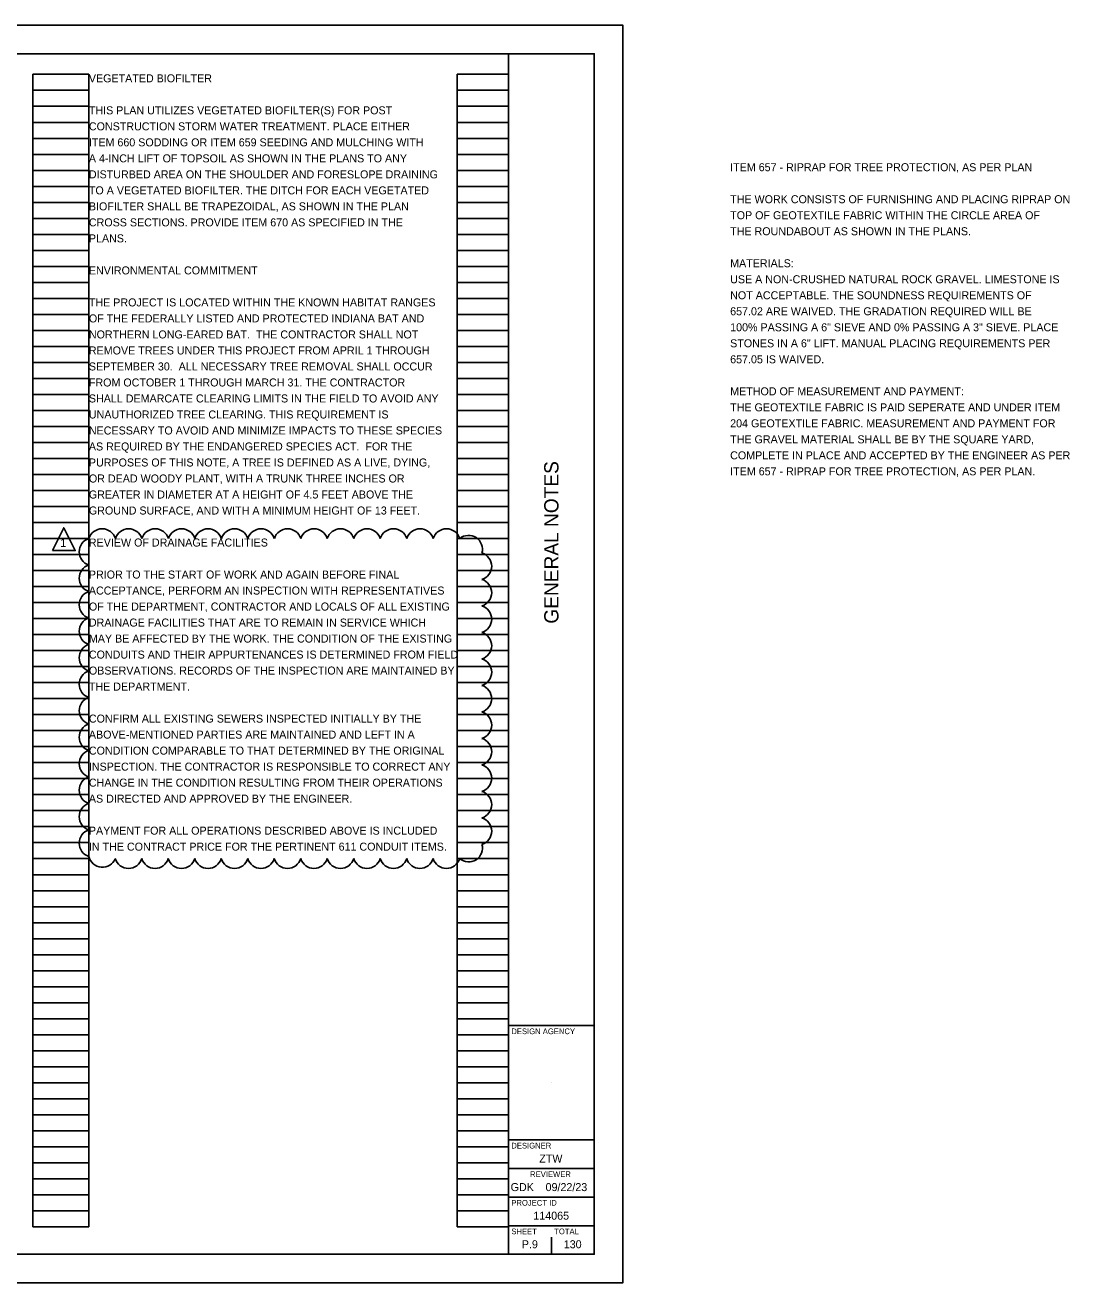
# Model space of a CAD drawing. Extents: x -20.9 to 41.8, y -2.3 to 41.6.
# Drawn here: x 23.55 to 41.82, y 0 to 22 of the extents above; entities that cross this region are included whole.
import ezdxf

# ---------------------------------------------------------------- set-up
doc = ezdxf.new("R2010")
doc.units = 0
for name, color, linetype in [('BR_P_Gen_Text', 7, 'Continuous'), ('SH_Border', 7, 'Continuous'), ('SH_Cut_Line', 7, 'Continuous'), ('SH_Data', 7, 'Continuous'), ('SH_Text', 7, 'Continuous')]:
    doc.layers.add(name, color=color, linetype=linetype)

msp = doc.modelspace()

# ---------------------------------------------------------------- linework, layer by layer
at = {"layer": 'BR_P_Gen_Text'}
msp.add_lwpolyline([(24.021, 12.808), (24.221, 13.208), (24.421, 12.808)], close=True, dxfattribs=at)
for centre, start, end in [((24.733, 12.788), 107.5, 252.5), ((24.892, 12.947), 17.5, 162.5), ((25.355, 12.947), 17.5, 162.5), ((25.819, 12.947), 17.5, 162.5), ((26.282, 12.947), 17.5, 162.5), ((26.745, 12.947), 17.5, 162.5), ((27.209, 12.947), 17.5, 162.5), ((27.672, 12.947), 17.5, 162.5), ((28.136, 12.947), 17.5, 162.5), ((28.599, 12.947), 17.5, 162.5), ((29.062, 12.947), 17.5, 162.5), ((29.526, 12.947), 17.5, 162.5), ((29.989, 12.947), 17.5, 162.5), ((30.453, 12.947), 17.5, 162.5), ((30.916, 12.947), 17.5, 162.5), ((31.302, 12.832), 344.4353, 129.4353), ((31.463, 12.535), 287.5, 72.5), ((24.733, 12.325), 107.5, 252.5), ((31.463, 12.072), 287.5, 72.5), ((24.733, 11.861), 107.5, 252.5), ((31.463, 11.609), 287.5, 72.5), ((24.733, 11.398), 107.5, 252.5), ((31.463, 11.145), 287.5, 72.5), ((24.733, 10.935), 107.5, 252.5), ((31.463, 10.682), 287.5, 72.5), ((24.733, 10.471), 107.5, 252.5), ((31.463, 10.218), 287.5, 72.5), ((24.733, 10.008), 107.5, 252.5), ((31.463, 9.755), 287.5, 72.5), ((24.733, 9.544), 107.5, 252.5), ((31.463, 9.291), 287.5, 72.5), ((24.733, 9.081), 107.5, 252.5), ((31.463, 8.828), 287.5, 72.5), ((24.733, 8.618), 107.5, 252.5), ((31.463, 8.365), 287.5, 72.5), ((24.733, 8.154), 107.5, 252.5), ((24.733, 7.691), 107.5, 252.5), ((31.463, 7.901), 287.5, 72.5), ((31.302, 7.606), 230.0934, 15.0934), ((24.897, 7.512), 192.6693, 337.6693), ((25.353, 7.493), 197.5, 342.5), ((25.817, 7.493), 197.5, 342.5), ((26.28, 7.493), 197.5, 342.5), ((26.744, 7.493), 197.5, 342.5), ((27.207, 7.493), 197.5, 342.5), ((27.67, 7.493), 197.5, 342.5), ((28.134, 7.493), 197.5, 342.5), ((28.597, 7.493), 197.5, 342.5), ((29.061, 7.493), 197.5, 342.5), ((29.524, 7.493), 197.5, 342.5), ((29.988, 7.493), 197.5, 342.5), ((30.451, 7.493), 197.5, 342.5), ((30.914, 7.493), 197.5, 342.5)]:
    msp.add_arc(centre, 0.243, start, end, dxfattribs=at)
at = {"layer": 'SH_Cut_Line'}
for p, q in [((32, 0.5), (32, 21.5)), ((32, 4.5), (33.5, 4.5)), ((32, 2.5), (33.5, 2.5)), ((32, 2), (33.5, 2)), ((32, 1.5), (33.5, 1.5)), ((32, 1), (33.5, 1))]:
    msp.add_line(p, q, dxfattribs=at)
msp.add_lwpolyline([(1.5, 21.5), (33.5, 21.5), (33.5, 0.5), (1.5, 0.5)], close=True, dxfattribs=at)
at = {"layer": 'SH_Data'}
for p, q in [((23.68, 0.98), (23.68, 21.14)), ((23.68, 21.14), (24.66, 21.14)), ((24.66, 0.98), (24.66, 21.14)), ((31.1, 0.98), (31.1, 21.14)), ((31.1, 21.14), (32, 21.14)), ((32, 0.98), (32, 21.14)), ((23.68, 20.86), (24.66, 20.86)), ((31.1, 20.86), (32, 20.86)), ((23.68, 20.58), (24.66, 20.58)), ((31.1, 20.58), (32, 20.58)), ((23.68, 20.3), (24.66, 20.3)), ((31.1, 20.3), (32, 20.3)), ((23.68, 20.02), (24.66, 20.02)), ((31.1, 20.02), (32, 20.02)), ((23.68, 19.74), (24.66, 19.74)), ((31.1, 19.74), (32, 19.74)), ((23.68, 19.46), (24.66, 19.46)), ((31.1, 19.46), (32, 19.46)), ((23.68, 19.18), (24.66, 19.18)), ((31.1, 19.18), (32, 19.18)), ((23.68, 18.9), (24.66, 18.9)), ((31.1, 18.9), (32, 18.9)), ((23.68, 18.62), (24.66, 18.62)), ((31.1, 18.62), (32, 18.62)), ((23.68, 18.34), (24.66, 18.34)), ((31.1, 18.34), (32, 18.34)), ((23.68, 18.06), (24.66, 18.06)), ((31.1, 18.06), (32, 18.06)), ((23.68, 17.78), (24.66, 17.78)), ((31.1, 17.78), (32, 17.78)), ((23.68, 17.5), (24.66, 17.5)), ((31.1, 17.5), (32, 17.5)), ((23.68, 17.22), (24.66, 17.22)), ((31.1, 17.22), (32, 17.22)), ((23.68, 16.94), (24.66, 16.94)), ((31.1, 16.94), (32, 16.94)), ((23.68, 16.66), (24.66, 16.66)), ((31.1, 16.66), (32, 16.66)), ((23.68, 16.38), (24.66, 16.38)), ((31.1, 16.38), (32, 16.38)), ((23.68, 16.1), (24.66, 16.1)), ((31.1, 16.1), (32, 16.1)), ((23.68, 15.82), (24.66, 15.82)), ((31.1, 15.82), (32, 15.82)), ((23.68, 15.54), (24.66, 15.54)), ((31.1, 15.54), (32, 15.54)), ((23.68, 15.26), (24.66, 15.26)), ((31.1, 15.26), (32, 15.26)), ((23.68, 14.98), (24.66, 14.98)), ((31.1, 14.98), (32, 14.98)), ((23.68, 14.7), (24.66, 14.7)), ((31.1, 14.7), (32, 14.7)), ((23.68, 14.42), (24.66, 14.42)), ((31.1, 14.42), (32, 14.42)), ((23.68, 14.14), (24.66, 14.14)), ((31.1, 14.14), (32, 14.14)), ((23.68, 13.86), (24.66, 13.86)), ((31.1, 13.86), (32, 13.86)), ((23.68, 13.58), (24.66, 13.58)), ((31.1, 13.58), (32, 13.58)), ((23.68, 13.3), (24.66, 13.3)), ((31.1, 13.3), (32, 13.3)), ((23.68, 13.02), (24.66, 13.02)), ((31.1, 13.02), (32, 13.02)), ((23.68, 12.74), (24.66, 12.74)), ((31.1, 12.74), (32, 12.74)), ((23.68, 12.46), (24.66, 12.46)), ((31.1, 12.46), (32, 12.46)), ((23.68, 12.18), (24.66, 12.18)), ((31.1, 12.18), (32, 12.18)), ((23.68, 11.9), (24.66, 11.9)), ((31.1, 11.9), (32, 11.9)), ((23.68, 11.62), (24.66, 11.62)), ((31.1, 11.62), (32, 11.62)), ((23.68, 11.34), (24.66, 11.34)), ((31.1, 11.34), (32, 11.34)), ((23.68, 11.06), (24.66, 11.06)), ((31.1, 11.06), (32, 11.06)), ((23.68, 10.78), (24.66, 10.78)), ((31.1, 10.78), (32, 10.78)), ((23.68, 10.5), (24.66, 10.5)), ((31.1, 10.5), (32, 10.5)), ((23.68, 10.22), (24.66, 10.22)), ((31.1, 10.22), (32, 10.22)), ((23.68, 9.94), (24.66, 9.94)), ((31.1, 9.94), (32, 9.94)), ((23.68, 9.66), (24.66, 9.66)), ((31.1, 9.66), (32, 9.66)), ((23.68, 9.38), (24.66, 9.38)), ((31.1, 9.38), (32, 9.38)), ((23.68, 9.1), (24.66, 9.1)), ((31.1, 9.1), (32, 9.1)), ((23.68, 8.82), (24.66, 8.82)), ((31.1, 8.82), (32, 8.82)), ((23.68, 8.54), (24.66, 8.54)), ((31.1, 8.54), (32, 8.54)), ((23.68, 8.26), (24.66, 8.26)), ((31.1, 8.26), (32, 8.26)), ((23.68, 7.98), (24.66, 7.98)), ((31.1, 7.98), (32, 7.98)), ((23.68, 7.7), (24.66, 7.7)), ((31.1, 7.7), (32, 7.7)), ((23.68, 7.42), (24.66, 7.42)), ((31.1, 7.42), (32, 7.42)), ((23.68, 7.14), (24.66, 7.14)), ((31.1, 7.14), (32, 7.14)), ((23.68, 6.86), (24.66, 6.86)), ((31.1, 6.86), (32, 6.86)), ((23.68, 6.58), (24.66, 6.58)), ((31.1, 6.58), (32, 6.58)), ((23.68, 6.3), (24.66, 6.3)), ((31.1, 6.3), (32, 6.3)), ((23.68, 6.02), (24.66, 6.02)), ((31.1, 6.02), (32, 6.02)), ((23.68, 5.74), (24.66, 5.74)), ((31.1, 5.74), (32, 5.74)), ((23.68, 5.46), (24.66, 5.46)), ((31.1, 5.46), (32, 5.46)), ((23.68, 5.18), (24.66, 5.18)), ((31.1, 5.18), (32, 5.18)), ((23.68, 4.9), (24.66, 4.9)), ((31.1, 4.9), (32, 4.9)), ((23.68, 4.62), (24.66, 4.62)), ((31.1, 4.62), (32, 4.62)), ((23.68, 4.34), (24.66, 4.34)), ((31.1, 4.34), (32, 4.34)), ((23.68, 4.06), (24.66, 4.06)), ((31.1, 4.06), (32, 4.06)), ((23.68, 3.78), (24.66, 3.78)), ((31.1, 3.78), (32, 3.78)), ((23.68, 3.5), (24.66, 3.5)), ((31.1, 3.5), (32, 3.5)), ((32.75, 3.5), (32.75, 3.5)), ((23.68, 3.22), (24.66, 3.22)), ((31.1, 3.22), (32, 3.22)), ((23.68, 2.94), (24.66, 2.94)), ((31.1, 2.94), (32, 2.94)), ((23.68, 2.66), (24.66, 2.66)), ((31.1, 2.66), (32, 2.66)), ((23.68, 2.38), (24.66, 2.38)), ((31.1, 2.38), (32, 2.38)), ((23.68, 2.1), (24.66, 2.1)), ((31.1, 2.1), (32, 2.1)), ((23.68, 1.82), (24.66, 1.82)), ((31.1, 1.82), (32, 1.82)), ((23.68, 1.54), (24.66, 1.54)), ((31.1, 1.54), (32, 1.54)), ((23.68, 1.26), (24.66, 1.26)), ((31.1, 1.26), (32, 1.26)), ((23.68, 0.98), (24.66, 0.98)), ((31.1, 0.98), (32, 0.98)), ((32.375, 0.675), (32.375, 0.675)), ((32.75, 0.5), (32.75, 0.8))]:
    msp.add_line(p, q, dxfattribs=at)
at = {"layer": 'SH_Text'}
msp.add_lwpolyline([(0, 0), (34, 0), (34, 22), (0, 22)], close=True, dxfattribs=at)

# ---------------------------------------------------------------- texts
at = {"layer": 'BR_P_Gen_Text'}
msp.add_text('1', height=0.14, dxfattribs=at).set_placement((24.159, 12.874))
at = {"layer": 'SH_Border'}
for s, p in [('VEGETATED BIOFILTER', (24.66, 21)), ('THIS PLAN UTILIZES VEGETATED BIOFILTER(S) FOR POST', (24.66, 20.44)), ('CONSTRUCTION STORM WATER TREATMENT. PLACE EITHER', (24.66, 20.16)), ('ITEM 660 SODDING OR ITEM 659 SEEDING AND MULCHING WITH', (24.66, 19.88)), ('A 4-INCH LIFT OF TOPSOIL AS SHOWN IN THE PLANS TO ANY', (24.66, 19.6)), ('ITEM 657 - RIPRAP FOR TREE PROTECTION, AS PER PLAN', (35.878, 19.445)), ('DISTURBED AREA ON THE SHOULDER AND FORESLOPE DRAINING', (24.66, 19.32)), ('TO A VEGETATED BIOFILTER. THE DITCH FOR EACH VEGETATED', (24.66, 19.04)), ('THE WORK CONSISTS OF FURNISHING AND PLACING RIPRAP ON ', (35.878, 18.885)), ('BIOFILTER SHALL BE TRAPEZOIDAL, AS SHOWN IN THE PLAN', (24.66, 18.76)), ('TOP OF GEOTEXTILE FABRIC WITHIN THE CIRCLE AREA OF', (35.878, 18.605)), ('CROSS SECTIONS. PROVIDE ITEM 670 AS SPECIFIED IN THE', (24.66, 18.48)), ('PLANS.', (24.66, 18.2)), ('THE ROUNDABOUT AS SHOWN IN THE PLANS.', (35.878, 18.325)), ('MATERIALS:', (35.878, 17.765)), ('ENVIRONMENTAL COMMITMENT', (24.66, 17.64)), ('USE A NON-CRUSHED NATURAL ROCK GRAVEL. LIMESTONE IS', (35.878, 17.485)), ('THE PROJECT IS LOCATED WITHIN THE KNOWN HABITAT RANGES ', (24.66, 17.08)), ('NOT ACCEPTABLE. THE SOUNDNESS REQUIREMENTS OF ', (35.878, 17.205)), ('OF THE FEDERALLY LISTED AND PROTECTED INDIANA BAT AND ', (24.66, 16.8)), ('657.02 ARE WAIVED. THE GRADATION REQUIRED WILL BE ', (35.878, 16.925)), ('100% PASSING A 6" SIEVE AND 0% PASSING A 3" SIEVE. PLACE', (35.878, 16.645)), ('NORTHERN LONG-EARED BAT.  THE CONTRACTOR SHALL NOT ', (24.66, 16.52)), ('STONES IN A 6" LIFT. MANUAL PLACING REQUIREMENTS PER', (35.878, 16.365)), ('REMOVE TREES UNDER THIS PROJECT FROM APRIL 1 THROUGH ', (24.66, 16.24)), ('SEPTEMBER 30.  ALL NECESSARY TREE REMOVAL SHALL OCCUR ', (24.66, 15.96)), ('657.05 IS WAIVED.', (35.878, 16.085)), ('FROM OCTOBER 1 THROUGH MARCH 31. THE CONTRACTOR ', (24.66, 15.68)), ('METHOD OF MEASUREMENT AND PAYMENT:', (35.878, 15.525)), ('SHALL DEMARCATE CLEARING LIMITS IN THE FIELD TO AVOID ANY ', (24.66, 15.4)), ('UNAUTHORIZED TREE CLEARING. THIS REQUIREMENT IS ', (24.66, 15.12)), ('THE GEOTEXTILE FABRIC IS PAID SEPERATE AND UNDER ITEM', (35.878, 15.245)), ('NECESSARY TO AVOID AND MINIMIZE IMPACTS TO THESE SPECIES ', (24.66, 14.84)), ('204 GEOTEXTILE FABRIC. MEASUREMENT AND PAYMENT FOR', (35.878, 14.965)), ('THE GRAVEL MATERIAL SHALL BE BY THE SQUARE YARD,', (35.878, 14.685)), ('AS REQUIRED BY THE ENDANGERED SPECIES ACT.  FOR THE ', (24.66, 14.56)), ('COMPLETE IN PLACE AND ACCEPTED BY THE ENGINEER AS PER ', (35.878, 14.405)), ('PURPOSES OF THIS NOTE, A TREE IS DEFINED AS A LIVE, DYING, ', (24.66, 14.28)), ('OR DEAD WOODY PLANT, WITH A TRUNK THREE INCHES OR ', (24.66, 14)), ('ITEM 657 - RIPRAP FOR TREE PROTECTION, AS PER PLAN.', (35.878, 14.125)), ('GREATER IN DIAMETER AT A HEIGHT OF 4.5 FEET ABOVE THE ', (24.66, 13.72)), ('GROUND SURFACE, AND WITH A MINIMUM HEIGHT OF 13 FEET. ', (24.66, 13.44)), ('REVIEW OF DRAINAGE FACILITIES', (24.66, 12.88)), ('PRIOR TO THE START OF WORK AND AGAIN BEFORE FINAL', (24.66, 12.32)), ('ACCEPTANCE, PERFORM AN INSPECTION WITH REPRESENTATIVES', (24.66, 12.04)), ('OF THE DEPARTMENT, CONTRACTOR AND LOCALS OF ALL EXISTING', (24.66, 11.76)), ('DRAINAGE FACILITIES THAT ARE TO REMAIN IN SERVICE WHICH', (24.66, 11.48)), ('MAY BE AFFECTED BY THE WORK. THE CONDITION OF THE EXISTING', (24.66, 11.2)), ('CONDUITS AND THEIR APPURTENANCES IS DETERMINED FROM FIELD', (24.66, 10.92)), ('OBSERVATIONS. RECORDS OF THE INSPECTION ARE MAINTAINED BY', (24.66, 10.64)), ('THE DEPARTMENT.', (24.66, 10.36)), ('CONFIRM ALL EXISTING SEWERS INSPECTED INITIALLY BY THE', (24.66, 9.8)), ('ABOVE-MENTIONED PARTIES ARE MAINTAINED AND LEFT IN A', (24.66, 9.52)), ('CONDITION COMPARABLE TO THAT DETERMINED BY THE ORIGINAL', (24.66, 9.24)), ('INSPECTION. THE CONTRACTOR IS RESPONSIBLE TO CORRECT ANY', (24.66, 8.96)), ('CHANGE IN THE CONDITION RESULTING FROM THEIR OPERATIONS', (24.66, 8.68)), ('AS DIRECTED AND APPROVED BY THE ENGINEER.', (24.66, 8.4)), ('PAYMENT FOR ALL OPERATIONS DESCRIBED ABOVE IS INCLUDED', (24.66, 7.84)), ('IN THE CONTRACT PRICE FOR THE PERTINENT 611 CONDUIT ITEMS.', (24.66, 7.56))]:
    msp.add_text(s, height=0.14, dxfattribs=at).set_placement(p)
at = {"layer": 'SH_Data'}
msp.add_text('GENERAL NOTES', height=0.25, rotation=90, dxfattribs=at).set_placement((32.875, 11.531))
for s, height, p in [('DESIGN AGENCY', 0.1, (32.05, 4.35)), ('DESIGNER', 0.1, (32.05, 2.35)), ('ZTW', 0.14, (32.539, 2.105)), ('REVIEWER', 0.1, (32.378, 1.85)), ('GDK', 0.14, (32.038, 1.605)), ('09/22/23', 0.14, (32.649, 1.605)), ('PROJECT ID', 0.1, (32.05, 1.35)), ('114065', 0.14, (32.435, 1.105)), ('SHEET', 0.1, (32.05, 0.85)), ('TOTAL', 0.1, (32.8, 0.85)), ('P.9', 0.14, (32.233, 0.605)), ('130', 0.14, (32.967, 0.605))]:
    msp.add_text(s, height=height, dxfattribs=at).set_placement(p)

doc.saveas('drawing.dxf')
